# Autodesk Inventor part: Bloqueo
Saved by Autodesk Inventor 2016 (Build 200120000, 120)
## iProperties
Created: 2017-06
Part Number: Bloqueo
Material: Generic
Document SubType Name: Modeling
Designer: Administrator
Appearance: Generic
Author: Administrator
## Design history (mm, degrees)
feature "Body1"
body "Solid1"
